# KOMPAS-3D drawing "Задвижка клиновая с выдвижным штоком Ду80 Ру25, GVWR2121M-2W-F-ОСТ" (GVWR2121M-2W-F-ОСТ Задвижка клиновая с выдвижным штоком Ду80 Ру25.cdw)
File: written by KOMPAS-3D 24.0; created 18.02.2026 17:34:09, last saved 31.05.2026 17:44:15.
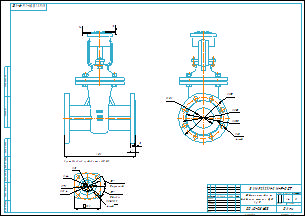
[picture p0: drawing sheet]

Document properties: Автор: R2D2; Форматы листов документа: A2; Полное имя файла: GVWR2121M-2W-F-ОСТ Задвижка клиновая с выдвижным штоком Ду80 Ру25.m3d; Масса: 24; Наименование: Задвижка клиновая с выдвижным штоком Ду80 Ру25; Количество листов документа: 1; Примечание: D040-08603

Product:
- Part/product: Задвижка клиновая с выдвижным штоком Ду80 Ру25  | designation GVWR2121M-2W-F-ОСТ
    Масса: 24
    Раздел спецификации: Прочие изделия
    Примечание: D040-08603

Views: Проекционный вид 2, Проекционный вид 3
Referenced files in E:\Работа\Зайцев\GVWR2121M-2W-F-ОСТ Задвижка клиновая с видвижным штоком Ду50-300 Ру16\DN80\: GVWR2121M-2W-F-ОСТ Задвижка клиновая с видвижным штоком Ду80 Ру16.m3d
Referenced files in E:\Работа\Зайцев\Для компаса\: чертеж DN.ru А3.cdt
Referenced files in E:\Работа\Зайцев\GVWR2121M-2W-F-ОСТ Задвижка клиновая 30с964нж DN.ru Ду50-300 Ру25\исходные материалы\DN80\DN80\: GVWR2121M-2W-F-ОСТ Задвижка клиновая с выдвижным штоком Ду80 Ру25.m3d
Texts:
  GVWR2121M-2W-F-ОСТ
  Присоединение привода тип АК (А)
  чертеж DN.ru А3.cdt
  Задвижка клиновая с
  выдвижным штоком Ду80
  Ру25
  Задвижка клиновая с выдвижным штоком Ду80 Ру25
  GVWR2121M-2W-F-ОСТ Задвижка клиновая с выдвижным штоком Ду80 Ру25
Dimensions and other numbers on the sheet: 0; 3; 4; 195; 80; 18; 4 отв.; 160; 135; 100; 5 кулачков; 5 впадин; 14(М12); 104; 70; 44; 32; 1:2; 1; 2; 24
